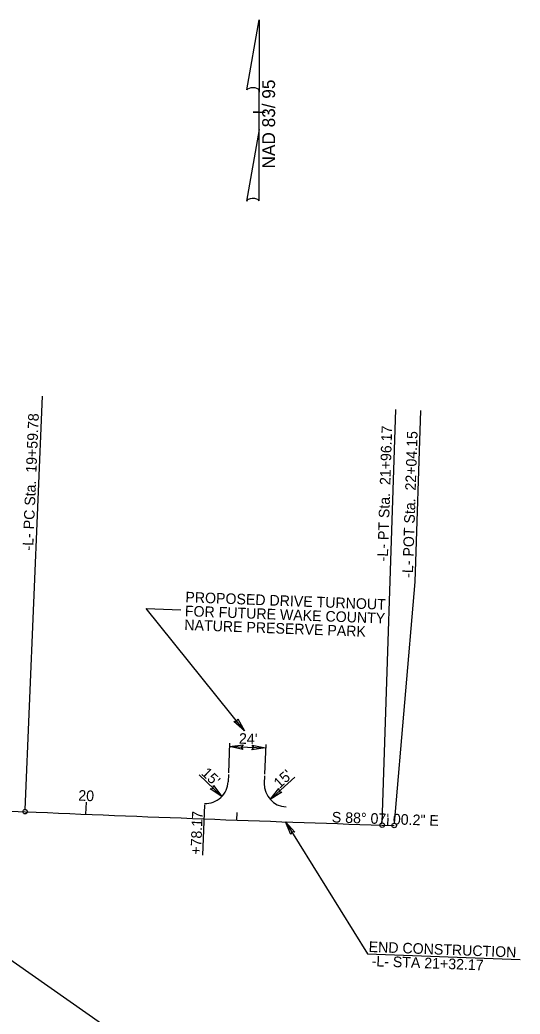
# Model space of a CAD drawing. Extents: x 2170295 to 2171718, y 723585 to 724580.
# Drawn here: x 2171357 to 2171688, y 723922 to 724580 of the extents above; entities that cross this region are included whole.
import ezdxf

# ---------------------------------------------------------------- set-up
doc = ezdxf.new("R2010")
doc.units = 0
for name, color, linetype in [('Prop Dimension', 7, 'Continuous'), ('Prop DSN Text', 7, 'Continuous'), ('Prop EOT', 7, 'Continuous'), ('Prop Horizontal Alignment', 7, 'Continuous'), ('Prop Horizontal Alignment Direction Label', 7, 'Continuous'), ('Prop Horizontal Alignment Station Label', 7, 'Continuous'), ('Prop Horizontal Alignment Tick Label', 7, 'Continuous'), ('Prop Horizontal Alignment Tick Large', 7, 'Continuous'), ('Prop Horizontal Alignment Tick Small', 7, 'Continuous'), ('Prop North Arrow NAD83 for Plan Sheets CELL', 7, 'Continuous'), ('Prop Terminator CELL', 7, 'Continuous')]:
    doc.layers.add(name, color=color, linetype=linetype)

msp = doc.modelspace()

# ---------------------------------------------------------------- linework, layer by layer
at = {"layer": 'Prop Dimension'}
for p, q in [((2171440.29, 724190.38), (2171463.21, 724189.52)), ((2171505.27, 724109.51), (2171440.29, 724190.38)), ((2171495.38, 724101.27), (2171494.66, 724081.62)), ((2171519.37, 724100.4), (2171518.65, 724080.75)), ((2171495.3, 724099.04), (2171519.28, 724098.17)), ((2171490.31, 724066.04), (2171475.32, 724080.35)), ((2171522.38, 724064.04), (2171538.52, 724078.88)), ((2171200.54, 724062.74), (2171439.97, 723895.67)), ((2171478.82, 724060.62), (2171477.61, 724027.23)), ((2171532.44, 724049.31), (2171586.67, 723962.05)), ((2171586.67, 723962.05), (2171687.67, 723958.27))]:
    msp.add_line(p, q, dxfattribs=at)
at = {"layer": 'Prop EOT'}
for p, q in [((2171494.63, 724080.7), (2171494.45, 724075.85)), ((2171518.61, 724079.82), (2171518.43, 724074.74))]:
    msp.add_line(p, q, dxfattribs=at)
for centre, start, end in [((2171479.46, 724076.4), 267.66289, 357.91126), ((2171533.42, 724074.19), 177.91126, 267.66289)]:
    msp.add_arc(centre, 15, start, end, dxfattribs=at)
at = {"layer": 'Prop Horizontal Alignment'}
for p, q in [((2170914.62, 724074.81), (2171360.17, 724056)), ((2171596.4, 724047.13), (2171604.38, 724046.87))]:
    msp.add_line(p, q, dxfattribs=at)
msp.add_arc((2172429.67, 749389.02), 25355.59, 267.582543, 268.116723, dxfattribs=at)
at = {"layer": 'Prop Horizontal Alignment Station Label'}
for p, q in [((2171360.24, 724057.5), (2171371.77, 724330.75)), ((2171596.45, 724048.63), (2171605.44, 724321.98)), ((2171618.33, 724207.91), (2171622.06, 724321.39)), ((2171604.51, 724048.36), (2171618.33, 724207.91))]:
    msp.add_line(p, q, dxfattribs=at)
for centre in [(2171360.17, 724056), (2171596.4, 724047.13), (2171604.38, 724046.87)]:
    msp.add_circle(centre, 1.5, dxfattribs=at)
at = {"layer": 'Prop Horizontal Alignment Tick Large'}
msp.add_line((2171400.36, 724054.33), (2171400.69, 724062.33), dxfattribs=at)
at = {"layer": 'Prop Horizontal Alignment Tick Small'}
for p, q in [((2171500.29, 724050.47), (2171500.47, 724055.47)), ((2171600.23, 724047), (2171600.39, 724052))]:
    msp.add_line(p, q, dxfattribs=at)
at = {"layer": 'Prop North Arrow NAD83 for Plan Sheets CELL'}
for p, q in [((2171506.77, 724533.28), (2171514.97, 724579.63)), ((2171515.02, 724579.63), (2171514.97, 724579.63)), ((2171515.02, 724579.63), (2171514.97, 724579.63)), ((2171515.02, 724579.63), (2171515.02, 724531.83)), ((2171515.02, 724507.03), (2171515.02, 724533.23)), ((2171515.02, 724531.83), (2171515.02, 724533.18)), ((2171511.02, 724518.63), (2171510.97, 724518.63)), ((2171514.57, 724518.63), (2171511.02, 724518.63)), ((2171511.07, 724518.63), (2171519.07, 724518.63)), ((2171515.02, 724507.03), (2171506.67, 724459.78)), ((2171515.07, 724459.98), (2171515.02, 724507.03))]:
    msp.add_line(p, q, dxfattribs=at)
for centre, start_param, end_param in [((2171510.91, 724532.78), 0.216388, 2.908219), ((2171510.91, 724459.61), 0.201328, 3.141593)]:
    msp.add_ellipse(centre, major_axis=(4.23, -0.03), ratio=0.461098, start_param=start_param, end_param=end_param, dxfattribs=at)
at = {"layer": 'Prop Terminator CELL'}
for points in [[(2171500.84, 724117.49), (2171505.27, 724109.51), (2171498.35, 724115.56), (2171500.32, 724115.66)], [(2171504.24, 724097.17), (2171495.3, 724099.04), (2171504.4, 724100.31), (2171503.19, 724098.76)], [(2171510.35, 724100.05), (2171519.28, 724098.17), (2171510.18, 724096.9), (2171511.39, 724098.46)], [(2171484.87, 724073.37), (2171490.31, 724066.04), (2171482.66, 724071.13), (2171484.6, 724071.49)], [(2171530.05, 724068.99), (2171522.38, 724064.04), (2171527.96, 724071.34), (2171528.19, 724069.39)], [(2171535.87, 724040.85), (2171532.44, 724049.31), (2171538.57, 724042.47), (2171536.61, 724042.6)]]:
    msp.add_lwpolyline(points, close=True, dxfattribs=at)

# ---------------------------------------------------------------- texts
at = {"layer": 'Prop DSN Text'}
for s, rotation, p in [('PROPOSED DRIVE TURNOUT', 357.85784, (2171466.11, 724194.49)), ('FOR FUTURE WAKE COUNTY', 357.85784, (2171465.77, 724185.32)), ('NATURE PRESERVE PARK', 357.85784, (2171465.43, 724176.15)), ("24'", 357.91126, (2171501.53, 724101.01)), ("15'", 316.32802, (2171476.29, 724080.91)), ("15'", 42.59836, (2171528.55, 724071.04)), ('+78.17', 87.58254, (2171476.51, 724027.46)), ('END CONSTRUCTION', 357.85784, (2171587.37, 723963.26)), ('-L- STA 21+32.17', 357.85784, (2171589.33, 723953.84))]:
    msp.add_text(s, height=7, rotation=rotation, dxfattribs=at).set_placement(p)
at = {"layer": 'Prop Horizontal Alignment Direction Label'}
msp.add_text('S 88%%d 07\' 00.2" E', height=7, rotation=358.11672, dxfattribs=at).set_placement((2171563.01, 724048.96))
at = {"layer": 'Prop Horizontal Alignment Station Label'}
for s, rotation, p in [('-L- PC Sta.  19+59.78', 87.58254, (2171365.46, 724228.59)), ('-L- PT Sta.  21+96.17', 88.11672, (2171600.13, 724221.48)), ('-L- POT Sta.  22+04.15', 88.11672, (2171616.69, 724210.58))]:
    msp.add_text(s, height=7, rotation=rotation, dxfattribs=at).set_placement(p)
at = {"layer": 'Prop Horizontal Alignment Tick Label'}
msp.add_text('20', height=7, rotation=357.67344, dxfattribs=at).set_placement((2171395.25, 724063.35))
at = {"layer": 'Prop North Arrow NAD83 for Plan Sheets CELL'}
msp.add_text('NAD 83/ 95', height=8.5, rotation=90, dxfattribs=at).set_placement((2171525.54, 724481.38))

doc.saveas('drawing.dxf')
